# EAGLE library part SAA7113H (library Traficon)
9bit video input processor
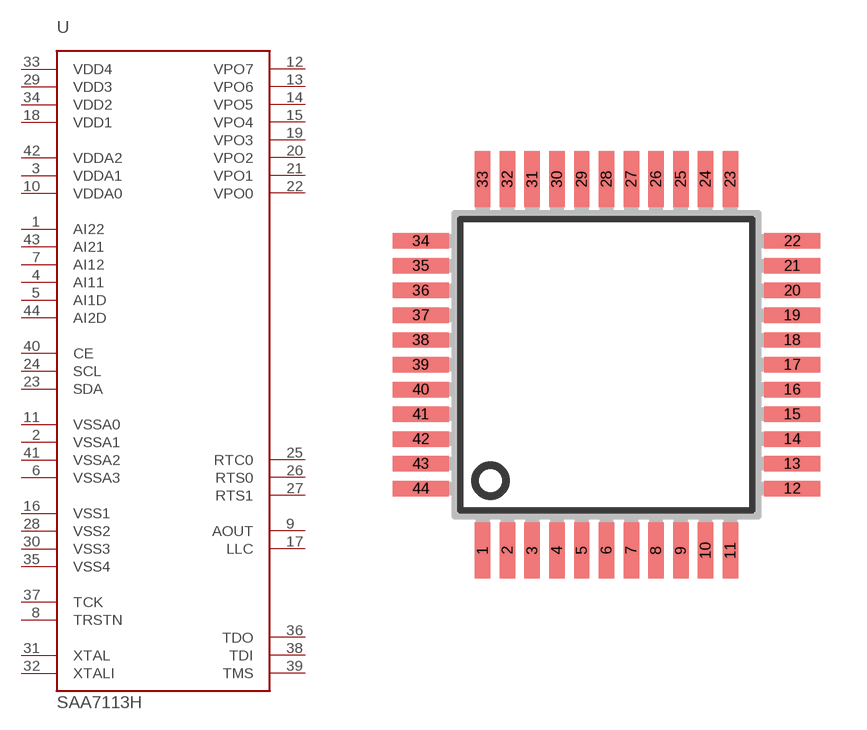
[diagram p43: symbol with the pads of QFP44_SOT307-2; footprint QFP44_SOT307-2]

Designator prefix U

## SAA7113H  [QFP44_SOT307-2]
1  AI22
2  VSSA1  pas
3  VDDA1  pas
4  AI11
5  AI1D
6  VSSA3  pas
7  AI12
8  TRSTN
9  AOUT
10  VDDA0  pas
11  VSSA0  pas
12  VPO7
13  VPO6
14  VPO5
15  VPO4
16  VSS1  pas
17  LLC
18  VDD1  pas
19  VPO3
20  VPO2
21  VPO1
22  VPO0
23  SDA
24  SCL
25  RTC0
26  RTS0
27  RTS1
28  VSS2  pas
29  VDD3  pas
30  VSS3  pas
31  XTAL
32  XTALI
33  VDD4  pas
34  VDD2  pas
35  VSS4  pas
36  TDO
37  TCK
38  TDI
39  TMS
40  CE
41  VSSA2  pas
42  VDDA2  pas
43  AI21
44  AI2D

## Footprint QFP44_SOT307-2 (pad centres in mm)
Plastic Quad Flat Package SOT307-2 44 leads (lead length 1.3 mm); body 10 x 10 x 1.75 mm SOT307-2 source: http://www.semiconductors.philips.com/ LQFP-MSQFP-QFP-SQFP-TQFP-REFLOW.pdf
smd 0.5 x 1.8: 1 -4,-6; 2 -3.2,-6; 3 -2.4,-6; 4 -1.6,-6; 5 -0.8,-6; 6 0,-6; 7 0.8,-6; 8 1.6,-6; 9 2.4,-6; 10 3.2,-6; 11 4,-6; 23 4,6; 24 3.2,6; 25 2.4,6; 26 1.6,6; 27 0.8,6; 28 0,6; 29 -0.8,6; 30 -1.6,6; 31 -2.4,6; 32 -3.2,6; 33 -4,6
smd 1.8 x 0.5: 12 6,-4; 13 6,-3.2; 14 6,-2.4; 15 6,-1.6; 16 6,-0.8; 17 6,0; 18 6,0.8; 19 6,1.6; 20 6,2.4; 21 6,3.2; 22 6,4; 34 -6,4; 35 -6,3.2; 36 -6,2.4; 37 -6,1.6; 38 -6,0.8; 39 -6,0; 40 -6,-0.8; 41 -6,-1.6; 42 -6,-2.4; 43 -6,-3.2; 44 -6,-4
